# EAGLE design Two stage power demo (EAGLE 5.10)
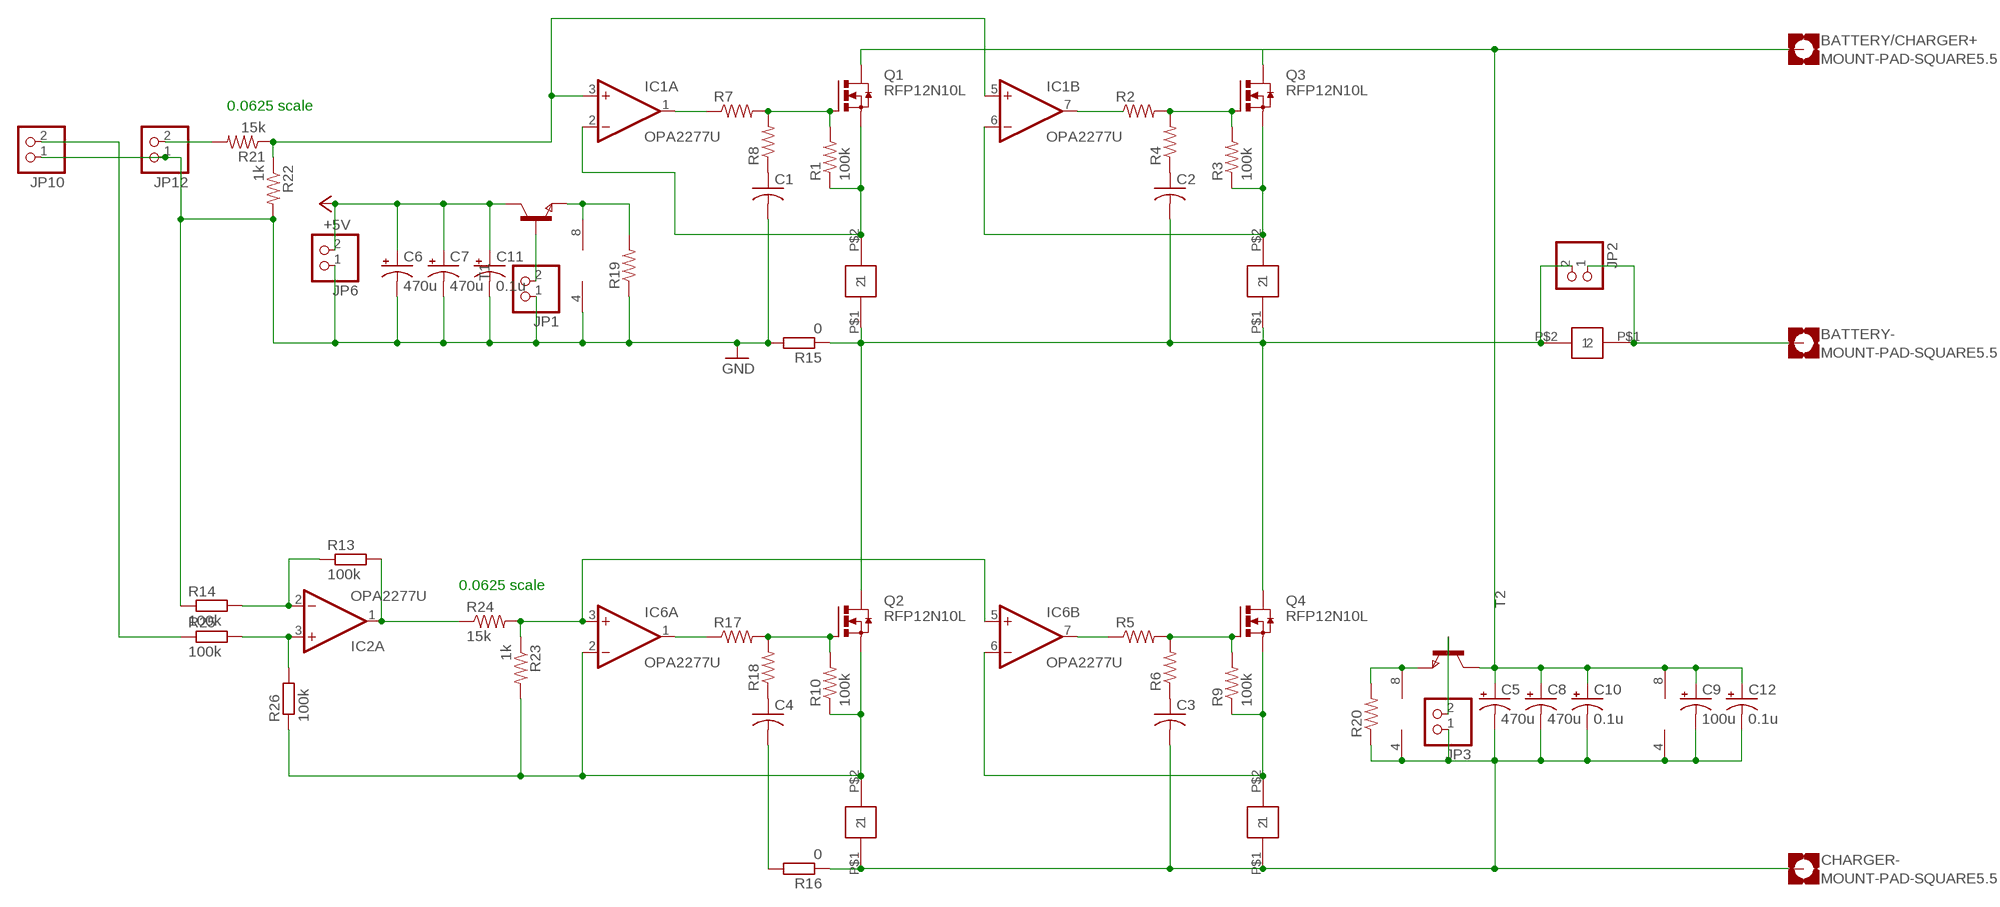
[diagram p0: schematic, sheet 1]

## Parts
BATTERY-  MOUNT-PAD-SQUARE5.5  [5,5-PAD-SQUARE]
BATTERY/CHARGER+  MOUNT-PAD-SQUARE5.5  [5,5-PAD-SQUARE]
C1  C-US150-054X183  [C150-054X183]
C2  C-US150-054X183  [C150-054X183]
C3  C-US150-054X183  [C150-054X183]
C4  C-US150-054X183  [C150-054X183]
C5  470u  CPOL-USE5-10.5  [E5-10,5]
C6  470u  CPOL-USE5-10.5  [E5-10,5]
C7  470u  CPOL-USE5-10.5  [E5-10,5]
C8  470u  CPOL-USE5-10.5  [E5-10,5]
C9  100u  CPOL-USE2.5-7  [E2,5-7]
C10  0.1u  CPOL-USE2-4  [E2-4]
C11  0.1u  CPOL-USE2-4  [E2-4]
C12  0.1u  CPOL-USE2-4  [E2-4]
CHARGER-  MOUNT-PAD-SQUARE5.5  [5,5-PAD-SQUARE]
IC1  OPA2277U  [SO08]
IC2  OPA2277U  [SO08]
IC6  OPA2277U  [SO08]
JP1  PINHD-1X2  [1X02]
JP2  PINHD-1X2  [1X02]
JP3  PINHD-1X2  [1X02]
JP6  PINHD-1X2  [1X02]
JP10  PINHD-1X2  [1X02]
JP12  PINHD-1X2  [1X02]
Q1  RFP12N10L  [TO220-W/657-20ABP]
Q2  RFP12N10L  [TO220-W/657-20ABP]
Q3  RFP12N10L  [TO220-W/657-20ABP]
Q4  RFP12N10L  [TO220-W/657-20ABP]
R1  100k  R-US_0411/12  [0411/12]
R2  R-US_0411/12  [0411/12]
R3  100k  R-US_0411/12  [0411/12]
R4  R-US_0411/12  [0411/12]
R5  R-US_0411/12  [0411/12]
R6  R-US_0411/12  [0411/12]
R7  R-US_0411/12  [0411/12]
R8  R-US_0411/12  [0411/12]
R9  100k  R-US_0411/12  [0411/12]
R10  100k  R-US_0411/12  [0411/12]
R13  100k  R-EU_R0805  [R0805]
R14  100k  R-EU_R0805  [R0805]
R15  0  R-EU_R0805  [R0805]
R16  0  R-EU_R0805  [R0805]
R17  R-US_0411/12  [0411/12]
R18  R-US_0411/12  [0411/12]
R19  R-US_0411/12  [0411/12]
R20  R-US_0411/12  [0411/12]
R21  15k  R-US_0411/12  [0411/12]
R22  1k  R-US_0411/12  [0411/12]
R23  1k  R-US_0411/12  [0411/12]
R24  15k  R-US_0411/12  [0411/12]
R25  100k  R-EU_R0805  [R0805]
R26  100k  R-EU_R0805  [R0805]
T1  NPNSOT323  [SOT323]
T2  NPNSOT323  [SOT323]
U$1  630HR050E  [630HR050E]
U$2  630HR050E  [630HR050E]
U$3  630HR050E  [630HR050E]
U$4  630HR050E  [630HR050E]
U$5  630HR050E  [630HR050E]

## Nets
+5V: C6.+ C7.+ C11.+ JP6.2 T1.1(C)
GND: C1.2 C6.- C7.- C11.- IC1.4(P:V-) JP1.1 JP6.1 JP10.1 JP12.1 R14.1 R15.2 R19.1 R22.2
LOAD: BATTERY/CHARGER+.B5,5(MOUNT) C5.+ C8.+ C9.+ C10.+ C12.+ IC2.8(P:V+) Q1.2(D) T2.1(C)
LOAD1: Q3.2(D)
LOAD2: C2.2 JP2.2 Q2.2(D) Q4.2(D) R15.1 U$1.P$1 U$2.P$2 U$4.P$1
N$1: IC1.7(B:OUT)
N$3: IC6.2(A:-IN) Q2.3(S) R10.1 R23.2 R26.1 U$3.P$2
N$4: IC2.2(A:-IN) R13.1 R14.2
N$5: BATTERY-.B5,5(MOUNT) JP2.1 U$2.P$1
N$6: IC1.8(P:V+) R19.2 T1.3(E)
N$7: JP1.2 T1.2(B)
N$8: IC2.1(A:OUT) R13.2 R24.1
N$9: IC1.6(B:-IN) Q3.3(S) R3.1 U$4.P$2
N$10: Q1.1(G) R1.2 R7.2 R8.2
N$11: IC1.3(A:+IN) IC1.5(B:+IN) R21.1 R22.1
N$12: IC6.6(B:-IN) Q4.3(S) R9.1 U$5.P$2
N$13: C1.1 R8.1
N$14: Q3.1(G) R2.2 R3.2 R4.2
N$15: C2.1 R4.1
N$16: Q4.1(G) R5.2 R6.2 R9.2
N$17: C3.2 C5.- C8.- C9.- C10.- C12.- CHARGER-.B5,5(MOUNT) IC2.4(P:V-) IC6.4(P:V-) JP3.1 R16.1 R20.1 U$3.P$1 U$5.P$1
N$18: C3.1 R6.1
N$19: IC2.3(A:+IN) R25.2 R26.2
N$20: Q2.1(G) R10.2 R17.2 R18.2
N$21: IC1.2(A:-IN) Q1.3(S) R1.1 U$1.P$2
N$22: C4.1 R18.1
N$23: IC1.1(A:OUT) R7.1
N$24: C4.2 R16.2
N$25: IC6.7(B:OUT) R5.1
N$26: IC6.1(A:OUT) R17.1
N$27: JP12.2 R21.2
N$28: JP10.2 R25.1
N$29: IC6.8(P:V+) R20.2 T2.3(E)
N$30: IC6.3(A:+IN) IC6.5(B:+IN) R23.1 R24.2
N$32: JP3.2 T2.2(B)
Unconnected: IC2.5(B:+IN) IC2.6(B:-IN) IC2.7(B:OUT) R2.1

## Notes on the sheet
- 0.0625 scale
- 0.0625 scale

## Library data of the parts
BATTERY- BATTERY/CHARGER+ CHARGER- = holes:MOUNT-PAD-SQUARE: MOUNTING PAD, square
C1-C4 = rcl:C-US: CAPACITOR, American symbol
C5-C12 = rcl:CPOL-US: POLARIZED CAPACITOR, American symbol
IC1 IC2 IC6 = linear:OPA2277: High Precision OPERATIONAL AMPLIFIERS REPLACES OP-07, OP-77, OP-177 Source: opa277.pdf
JP1-JP3 JP6 JP10 JP12 = pinhead:PINHD-1X2: PIN HEADER
Q1-Q4 = NEWPARTS:RFP12N10L: N-Channel Power MOSFET 100V; 12A; 0,2Ohm< Logic Level
R1-R10 R17-R24 = rcl:R-US_: RESISTOR, American symbol
R13-R16 R25 R26 = rcl:R-EU_: RESISTOR, European symbol
T1 T2 = zetex:NPNSOT323: NPN TRANSISTOR
U$1-U$5 = NEWPARTS:630HR050E

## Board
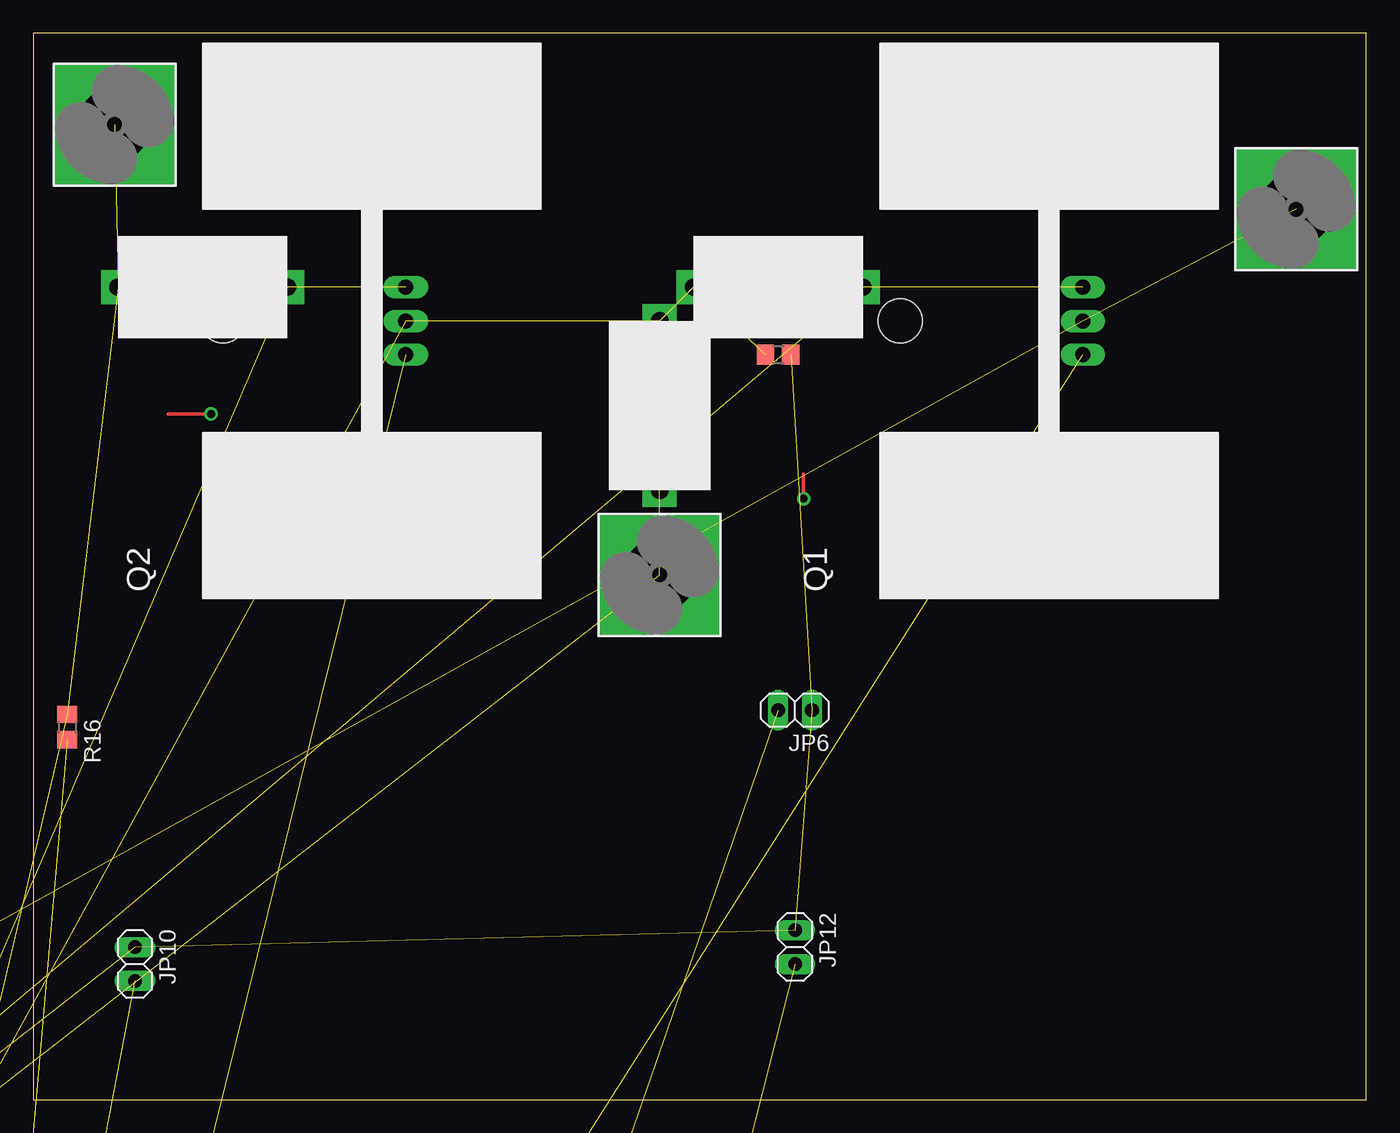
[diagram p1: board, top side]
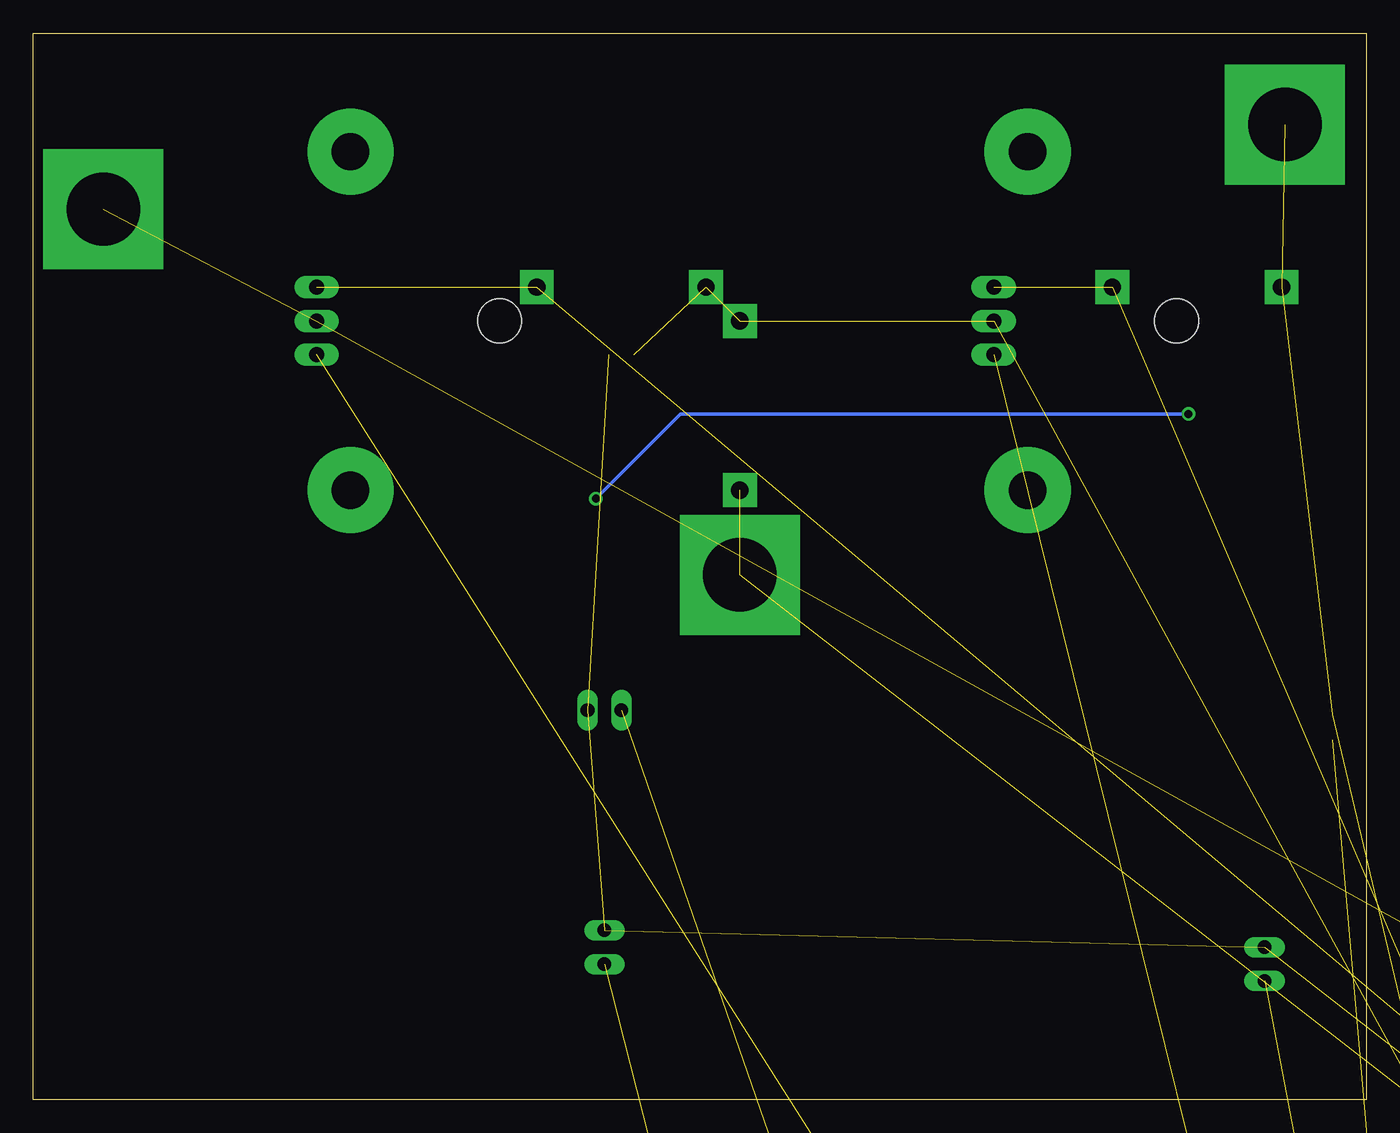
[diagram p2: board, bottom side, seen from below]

Size 100 x 80 mm. Coordinates in mm from the lower left corner, seen from the top.
Outline: 0,0 100,0 100,80 0,80 0,0
Copper layers (1*16): Top 0.035mm / dielectric 1.5mm / Bottom 0.035mm
Design rules "default": minimum track width 10mil, minimum drill 24mil, track to track 8mil, track to pad 8mil, pad to pad 8mil, via to via 8mil, smd to smd 8mil, copper to edge 40mil, drill to drill 8mil, minimum pad ring 10mil, minimum via ring 8mil, stop-mask expansion 4mil, vias tented up to drill 0mil, thermal gap 10mil

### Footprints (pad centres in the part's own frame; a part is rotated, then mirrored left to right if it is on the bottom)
5,5-PAD-SQUARE = drill 5.5 pad 9 square: B5,5 0,0
C150-054X183 = drill 1.016 octagon: 1 -7.493,0; 2 7.493,0
E5-10,5 = drill 1.016 pad 2.54 round: + -2.54,0 | drill 1.016 pad 2.54 octagon: - 2.54,0
E2,5-7 = drill 0.813 pad 1.6 round: + -1.27,0 | drill 0.813 pad 1.6 octagon: - 1.27,0
E2-4 = drill 0.813 pad 1.27 round: + -1.016,0 | drill 0.813 pad 1.27 octagon: - 1.016,0
SO08 = smd 0.6 x 2.2: 1 -1.905,-2.6; 2 -0.635,-2.6; 3 0.635,-2.6; 4 1.905,-2.6; 5 1.905,2.6; 6 0.635,2.6; 7 -0.635,2.6; 8 -1.905,2.6
1X02 = drill 1.016 long: 1 -1.27,0; 2 1.27,0
TO220-W/657-20ABP = drill 1.118 long: 1 -2.54,-2.54; 2 0,-2.54; 3 2.54,-2.54 | drill 2.8 pad 6.452 round: P$1 -12.7,0; P$2 12.7,0 | hole 3.302: 0,11.176
0411/12 = drill 0.914 octagon: 1 -6.35,0; 2 6.35,0
R0805 = smd 1.3 x 1.5: 1 -0.95,0; 2 0.95,0
SOT323 = smd 0.5 x 1: 1 0,0.9; 2 -0.65,-0.9; 3 0.65,-0.9
630HR050E = drill 1.3 pad 2.54 square: P$1 -6.35,0; P$2 6.35,0

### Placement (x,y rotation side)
BATTERY-  46.99,39.37 0 top
BATTERY/CHARGER+  94.74,66.8 0 top
C1  not placed on the board
C2  not placed on the board
C3  not placed on the board
C4  not placed on the board
C5  not placed on the board
C6  not placed on the board
C7  not placed on the board
C8  not placed on the board
C9  not placed on the board
C10  not placed on the board
C11  not placed on the board
C12  not placed on the board
CHARGER-  6.1,73.15 0 top
IC1  not placed on the board
IC2  not placed on the board
IC6  not placed on the board
JP1  not placed on the board
JP2  not placed on the board
JP3  not placed on the board
JP6  57.15,29.21 180 top
JP10  7.62,10.16 270 top
JP12  57.15,11.43 270 top
Q1  76.2,58.42 90 top
Q2  25.4,58.42 90 top
Q3  not placed on the board
Q4  not placed on the board
R1  not placed on the board
R2  not placed on the board
R3  not placed on the board
R4  not placed on the board
R5  not placed on the board
R6  not placed on the board
R7  not placed on the board
R8  not placed on the board
R9  not placed on the board
R10  not placed on the board
R13  not placed on the board
R14  not placed on the board
R15  55.88,55.88 0 top
R16  2.54,27.94 270 top
R17  not placed on the board
R18  not placed on the board
R19  not placed on the board
R20  not placed on the board
R21  not placed on the board
R22  not placed on the board
R23  not placed on the board
R24  not placed on the board
R25  not placed on the board
R26  not placed on the board
T1  not placed on the board
T2  not placed on the board
U$1  55.88,60.96 0 top
U$2  46.99,52.07 90 top
U$3  12.7,60.96 0 top
U$4  not placed on the board
U$5  not placed on the board

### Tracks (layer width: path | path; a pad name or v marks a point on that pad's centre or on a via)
+5V  (4 unrouted)
GND  (12 unrouted)
LOAD  (8 unrouted)
LOAD2  (7 unrouted)
N$3  (5 unrouted)
N$4  (2 unrouted)
N$5  (2 unrouted)
N$6  (2 unrouted)
N$7  (1 unrouted)
N$8  (2 unrouted)
N$9  (3 unrouted)
N$10  (3 unrouted)
N$11  (3 unrouted)
N$12  (3 unrouted)
N$13  (1 unrouted)
N$14  (3 unrouted)
N$15  (1 unrouted)
N$16  (3 unrouted)
N$17  (13 unrouted)
N$18  (1 unrouted)
N$19  (2 unrouted)
N$20  (3 unrouted)
N$21  (3 unrouted)
N$22  (1 unrouted)
N$23  (1 unrouted)
N$24  (1 unrouted)
N$25  (1 unrouted)
N$26  (1 unrouted)
N$27  (1 unrouted)
N$28  (1 unrouted)
N$29  (2 unrouted)
N$30  (3 unrouted)
N$32  (1 unrouted)
NC  (via drill 0.61)
  Top 0.254: 10.1,51.44 v13.34,51.44 | v57.78,45.09 57.78,46.93
  Bottom 0.254: v13.34,51.44 51.44,51.44 v57.78,45.09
